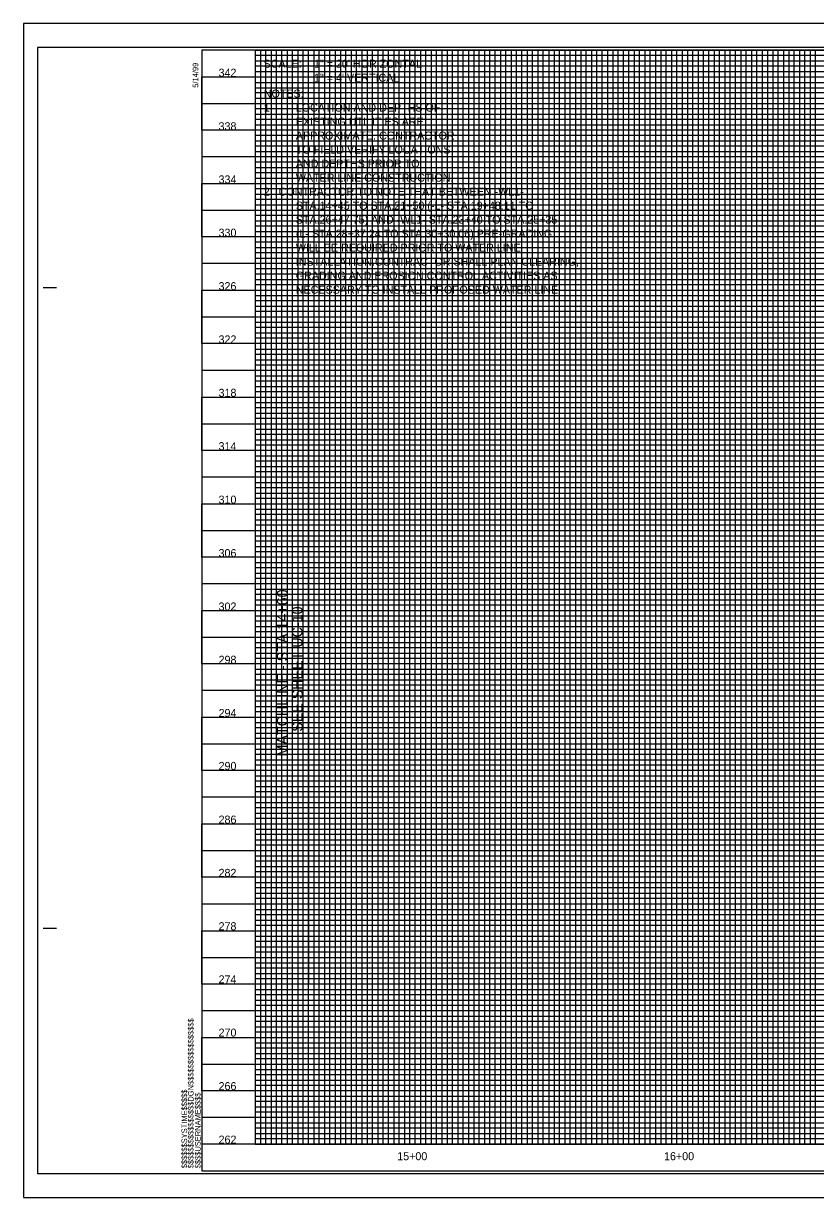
# Model space of a CAD drawing. Extents: x 3814791 to 3815465, y 1224203 to 1224643.
# Drawn here: x 3814791.3 to 3815088.1, y 1224203.2 to 1224643.2 of the extents above; entities that cross this region are included whole.
import ezdxf

# ---------------------------------------------------------------- set-up
doc = ezdxf.new("R2010")
doc.units = 0
for name, color, linetype in [('COGO Default Spiral', 7, 'Continuous'), ('Exist Roads EOP', 7, 'Continuous'), ('General Text and Text Box and Leader Line', 7, 'Continuous'), ('Pattern 49', 7, 'Continuous'), ('Profile Utility Text', 7, 'Continuous'), ('Scratch_Level_1', 7, 'Continuous'), ('Water Line Text and Text Box and Leader Line (St)', 7, 'Continuous'), ('Water Pump Station (St) CELL', 7, 'Continuous')]:
    doc.layers.add(name, color=color, linetype=linetype)

msp = doc.modelspace()

# ---------------------------------------------------------------- linework, layer by layer
at = {"layer": 'COGO Default Spiral'}
msp.add_line((3814898.11, 1224523.21), (3814898.11, 1224283.21), dxfattribs=at)
at = {"layer": 'Exist Roads EOP'}
for p, q in [((3814878.11, 1224633.21), (3815378.11, 1224633.21)), ((3815438.11, 1224561.21), (3814878.11, 1224561.21)), ((3814878.11, 1224561.21), (3814878.11, 1224559.21)), ((3814878.11, 1224559.21), (3815438.11, 1224559.21)), ((3815438.11, 1224551.21), (3814878.11, 1224551.21)), ((3814798.71, 1224544.21), (3814803.71, 1224544.21)), ((3814798.71, 1224304.21), (3814803.71, 1224304.21)), ((3815458.11, 1224223.21), (3814858.11, 1224223.21)), ((3814878.11, 1224223.21), (3815438.11, 1224223.21)), ((3814858.11, 1224213.21), (3814858.11, 1224213.21)), ((3814858.11, 1224213.21), (3814858.11, 1224213.21)), ((3814858.11, 1224213.21), (3814858.11, 1224213.21)), ((3814858.11, 1224213.21), (3814858.11, 1224213.21)), ((3814858.11, 1224213.21), (3814858.11, 1224213.21)), ((3814858.11, 1224213.21), (3814858.11, 1224213.21))]:
    msp.add_line(p, q, dxfattribs=at)
for points in [[(3815458.11, 1224633.21), (3814858.11, 1224633.21), (3814858.11, 1224213.21), (3815458.11, 1224213.21)], [(3814878.11, 1224633.21), (3814878.11, 1224223.21), (3815438.11, 1224223.21), (3815438.11, 1224578.19), (3815378.11, 1224578.19), (3815378.11, 1224633.21)]]:
    msp.add_lwpolyline(points, close=True, dxfattribs=at)
for points in [[(3814878.11, 1224633.21), (3814878.11, 1224223.21), (3814898.11, 1224223.21), (3814898.11, 1224633.21), (3814918.11, 1224633.21), (3814918.11, 1224223.21), (3814938.11, 1224223.21), (3814938.11, 1224633.21), (3814958.11, 1224633.21), (3814958.11, 1224223.21), (3814978.11, 1224223.21), (3814978.11, 1224633.21), (3814998.11, 1224633.21), (3814998.11, 1224223.21), (3815018.11, 1224223.21), (3815018.11, 1224633.21), (3815038.11, 1224633.21), (3815038.11, 1224223.21), (3815058.11, 1224223.21), (3815058.11, 1224633.21), (3815078.11, 1224633.21), (3815078.11, 1224223.21), (3815098.11, 1224223.21)], [(3814878.11, 1224633.21), (3814880.11, 1224633.21), (3814880.11, 1224223.21), (3814882.11, 1224223.21), (3814882.11, 1224633.21), (3814884.11, 1224633.21), (3814884.11, 1224223.21), (3814886.11, 1224223.21), (3814886.11, 1224633.21), (3814890.11, 1224633.21), (3814890.11, 1224223.21), (3814892.11, 1224223.21), (3814892.11, 1224633.21), (3814894.11, 1224633.21), (3814894.11, 1224223.21), (3814896.11, 1224223.21), (3814896.11, 1224633.21), (3814900.11, 1224633.21), (3814900.11, 1224223.21), (3814902.11, 1224223.21), (3814902.11, 1224633.21), (3814904.11, 1224633.21), (3814904.11, 1224223.21), (3814906.11, 1224223.21), (3814906.11, 1224633.21), (3814910.11, 1224633.21), (3814910.11, 1224223.21), (3814912.11, 1224223.21), (3814912.11, 1224633.21), (3814914.11, 1224633.21), (3814914.11, 1224223.21), (3814916.11, 1224223.21), (3814916.11, 1224633.21), (3814920.11, 1224633.21), (3814920.11, 1224223.21), (3814922.11, 1224223.21), (3814922.11, 1224633.21), (3814924.11, 1224633.21), (3814924.11, 1224223.21), (3814926.11, 1224223.21), (3814926.11, 1224633.21), (3814930.11, 1224633.21), (3814930.11, 1224223.21), (3814932.11, 1224223.21), (3814932.11, 1224633.21), (3814934.11, 1224633.21), (3814934.11, 1224223.21), (3814936.11, 1224223.21), (3814936.11, 1224633.21), (3814940.11, 1224633.21), (3814940.11, 1224223.21), (3814942.11, 1224223.21), (3814942.11, 1224633.21), (3814944.11, 1224633.21), (3814944.11, 1224223.21)], [(3815378.09, 1224631.21), (3814878.11, 1224631.21), (3814878.11, 1224629.21), (3815378.09, 1224629.21)], [(3814888.11, 1224223.21), (3814888.11, 1224633.21), (3814908.11, 1224633.21), (3814908.11, 1224223.21), (3814928.11, 1224223.21), (3814928.11, 1224633.21), (3814948.11, 1224633.21), (3814948.11, 1224223.21), (3814968.11, 1224223.21), (3814968.11, 1224633.21), (3814988.11, 1224633.21), (3814988.11, 1224223.21), (3815008.11, 1224223.21), (3815008.11, 1224633.21), (3815028.11, 1224633.21), (3815028.11, 1224223.21), (3815048.11, 1224223.21), (3815048.11, 1224633.21), (3815068.11, 1224633.21), (3815068.11, 1224223.21), (3815088.11, 1224223.21), (3815088.11, 1224633.21)], [(3814944.11, 1224223.21), (3814946.11, 1224223.21), (3814946.11, 1224633.21), (3814950.11, 1224633.21), (3814950.11, 1224223.21), (3814952.11, 1224223.21), (3814952.11, 1224633.21), (3814954.11, 1224633.21), (3814954.11, 1224223.21), (3814956.11, 1224223.21), (3814956.11, 1224633.21), (3814960.11, 1224633.21), (3814960.11, 1224223.21), (3814962.11, 1224223.21), (3814962.11, 1224633.21), (3814962.11, 1224633.21), (3814964.11, 1224633.21), (3814964.11, 1224223.21), (3814966.11, 1224223.21), (3814966.11, 1224633.21), (3814970.11, 1224633.21), (3814970.11, 1224223.21), (3814972.11, 1224223.21), (3814972.11, 1224633.21), (3814974.11, 1224633.21), (3814974.11, 1224223.21), (3814976.11, 1224223.21), (3814976.11, 1224633.21), (3814980.11, 1224633.21), (3814980.11, 1224223.21), (3814982.11, 1224223.21), (3814982.11, 1224633.21), (3814984.11, 1224633.21), (3814984.11, 1224223.21), (3814986.11, 1224223.21), (3814986.11, 1224633.21), (3814990.11, 1224633.21), (3814990.11, 1224223.21), (3814992.11, 1224223.21), (3814992.11, 1224633.21), (3814994.11, 1224633.21), (3814994.11, 1224223.21), (3814996.11, 1224223.21), (3814996.11, 1224633.21), (3815000.11, 1224633.21), (3815000.11, 1224223.21), (3815002.11, 1224223.21), (3815002.11, 1224633.21), (3815004.11, 1224633.21), (3815004.11, 1224223.21), (3815006.11, 1224223.21), (3815006.11, 1224633.21), (3815010.11, 1224633.21), (3815010.11, 1224223.21), (3815016.11, 1224223.21), (3815016.11, 1224633.21), (3815020.11, 1224633.21), (3815020.11, 1224223.21), (3815022.11, 1224223.21), (3815022.11, 1224633.21), (3815024.11, 1224633.21), (3815024.11, 1224223.21), (3815026.11, 1224223.21), (3815026.11, 1224633.21), (3815030.11, 1224633.21), (3815030.11, 1224223.21), (3815032.11, 1224223.21), (3815032.11, 1224633.21), (3815034.11, 1224633.21), (3815034.11, 1224223.21), (3815036.11, 1224223.21), (3815036.11, 1224633.21), (3815040.11, 1224633.21), (3815040.11, 1224223.21), (3815042.11, 1224223.21), (3815042.11, 1224633.21), (3815044.11, 1224633.21), (3815044.11, 1224223.21), (3815046.11, 1224223.21), (3815046.11, 1224633.21), (3815050.11, 1224633.21), (3815050.11, 1224223.21), (3815052.11, 1224223.21), (3815052.11, 1224633.21), (3815054.11, 1224633.21), (3815054.11, 1224223.21), (3815056.11, 1224223.21), (3815056.11, 1224633.21), (3815060.11, 1224633.21), (3815060.11, 1224223.21), (3815062.11, 1224223.21), (3815062.11, 1224633.21), (3815064.11, 1224633.21), (3815064.11, 1224223.21), (3815066.11, 1224223.21), (3815066.11, 1224633.21), (3815070.11, 1224633.21), (3815070.11, 1224223.21)], [(3815012.11, 1224633.21), (3815012.11, 1224223.21), (3815014.11, 1224223.21), (3815014.11, 1224633.21)], [(3815012.11, 1224632.97), (3815012.11, 1224223.21), (3815014.11, 1224223.21), (3815014.11, 1224632.97)], [(3815072.11, 1224633.21), (3815072.11, 1224223.21), (3815074.11, 1224223.21), (3815074.11, 1224633.21), (3815076.11, 1224633.21), (3815076.11, 1224223.21), (3815080.11, 1224223.21), (3815080.11, 1224633.21), (3815082.11, 1224633.21), (3815082.11, 1224223.21), (3815084.11, 1224223.21), (3815084.11, 1224633.21), (3815086.11, 1224633.21), (3815086.11, 1224223.21)], [(3815378.09, 1224627.21), (3814878.11, 1224627.21), (3814878.11, 1224625.21), (3815378.09, 1224625.21)], [(3815378.09, 1224603.21), (3814858.15, 1224603.21), (3814858.15, 1224623.19), (3815378.09, 1224623.19)], [(3815378.09, 1224620.91), (3814878.11, 1224620.91)], [(3815378.09, 1224618.91), (3814878.11, 1224618.91)], [(3815378.09, 1224617.21), (3814878.11, 1224617.21), (3814878.11, 1224615.21), (3815378.09, 1224615.21)], [(3814858.11, 1224613.21), (3815378.09, 1224613.21)], [(3815378.09, 1224611.21), (3814878.11, 1224611.21), (3814878.11, 1224609.21), (3815378.09, 1224609.21)], [(3815378.11, 1224607.21), (3814878.11, 1224607.21), (3814878.11, 1224605.21), (3815378.09, 1224605.21)], [(3815378.09, 1224601.21), (3814878.11, 1224601.21), (3814878.11, 1224599.21), (3815378.09, 1224599.21)], [(3815378.09, 1224597.21), (3814878.11, 1224597.21), (3814878.11, 1224595.21), (3815378.09, 1224595.21)], [(3815378.09, 1224593.21), (3814858.11, 1224593.21), (3814858.11, 1224573.19), (3815458.11, 1224573.19)], [(3815378.09, 1224591.21), (3814878.11, 1224591.21), (3814878.11, 1224589.21), (3815378.09, 1224589.21)], [(3815378.09, 1224587.21), (3814878.11, 1224587.21), (3814878.11, 1224585.21), (3815378.09, 1224585.21)], [(3815458.11, 1224563.21), (3814858.11, 1224563.21), (3814858.11, 1224583.21), (3815378.09, 1224583.21)], [(3815378.09, 1224581.21), (3814878.11, 1224581.21), (3814878.11, 1224579.21), (3815378.09, 1224579.21)], [(3815438.11, 1224577.21), (3814878.11, 1224577.21), (3814878.11, 1224577.21), (3814878.11, 1224569.21), (3815438.11, 1224569.21)], [(3814878.11, 1224575.21), (3815438.11, 1224575.21)], [(3815438.11, 1224571.21), (3814878.11, 1224571.21)], [(3815438.11, 1224567.21), (3814878.11, 1224567.21), (3814878.11, 1224565.21), (3815438.11, 1224565.21)], [(3815438.11, 1224557.21), (3814878.11, 1224557.21), (3814878.11, 1224555.21), (3815438.11, 1224555.21)], [(3815458.11, 1224553.21), (3814858.11, 1224553.21), (3814858.11, 1224533.21), (3815458.11, 1224533.21)], [(3815438.11, 1224549.21), (3814878.11, 1224549.21), (3814878.11, 1224547.21), (3815438.11, 1224547.21)], [(3815458.11, 1224523.21), (3814858.11, 1224523.21), (3814858.11, 1224543.21), (3815458.11, 1224543.21)], [(3815438.11, 1224545.21), (3814878.11, 1224545.21)], [(3814878.11, 1224541.21), (3815438.11, 1224541.21)], [(3815438.11, 1224539.21), (3814878.11, 1224539.21), (3814878.11, 1224537.21), (3815438.11, 1224537.21)], [(3815438.11, 1224535.21), (3814878.11, 1224535.21), (3814878.11, 1224531.21), (3815438.11, 1224531.21)], [(3815438.11, 1224529.21), (3814878.11, 1224529.21), (3814878.11, 1224527.21), (3815438.11, 1224527.21)], [(3815438.11, 1224525.21), (3814878.11, 1224525.21), (3814878.11, 1224521.21), (3815438.11, 1224521.21)], [(3815438.11, 1224519.21), (3814878.11, 1224519.21), (3814878.11, 1224517.21), (3815438.11, 1224517.21)], [(3815458.11, 1224513.21), (3814858.11, 1224513.21), (3814858.11, 1224493.21), (3815458.11, 1224493.21)], [(3815438.11, 1224515.21), (3814878.11, 1224515.21), (3814878.11, 1224511.21), (3815438.11, 1224511.21)], [(3815438.11, 1224509.21), (3814878.11, 1224509.21), (3814878.11, 1224507.21), (3815438.11, 1224507.21)], [(3815458.11, 1224483.21), (3814858.11, 1224483.21), (3814858.11, 1224503.21), (3815458.11, 1224503.21)], [(3815438.11, 1224505.21), (3814878.11, 1224505.21), (3814878.11, 1224501.21), (3815438.11, 1224501.21)], [(3815438.11, 1224499.21), (3814878.11, 1224499.21), (3814878.11, 1224497.21), (3815438.11, 1224497.21)], [(3815438.11, 1224495.21), (3814878.11, 1224495.21), (3814878.11, 1224491.21), (3815438.11, 1224491.21)], [(3815438.11, 1224489.21), (3814878.11, 1224489.21), (3814878.11, 1224487.21), (3815438.11, 1224487.21)], [(3815438.11, 1224485.21), (3814878.11, 1224485.21), (3814878.11, 1224481.21), (3815438.11, 1224481.21)], [(3815438.11, 1224479.21), (3814878.11, 1224479.21), (3814878.11, 1224477.21), (3815438.11, 1224477.21)], [(3815458.11, 1224473.21), (3814858.11, 1224473.21), (3814858.11, 1224453.21), (3815458.11, 1224453.21)], [(3815438.11, 1224475.21), (3814878.11, 1224475.21), (3814878.11, 1224471.21), (3815438.11, 1224471.21)], [(3815438.11, 1224469.21), (3814878.11, 1224469.21), (3814878.11, 1224467.21), (3815438.11, 1224467.21)], [(3815458.11, 1224443.21), (3814858.11, 1224443.21), (3814858.11, 1224463.21), (3815458.11, 1224463.21)], [(3815438.11, 1224465.21), (3814878.11, 1224465.21), (3814878.11, 1224461.21), (3815438.11, 1224461.21)], [(3815438.11, 1224459.21), (3814878.11, 1224459.21), (3814878.11, 1224457.21), (3815438.11, 1224457.21)], [(3815438.11, 1224455.21), (3814878.11, 1224455.21), (3814878.11, 1224451.21), (3815438.11, 1224451.21)], [(3815438.11, 1224449.21), (3814878.11, 1224449.21), (3814878.11, 1224447.21), (3815438.11, 1224447.21)], [(3815438.11, 1224445.21), (3814878.11, 1224445.21), (3814878.11, 1224441.21), (3815438.11, 1224441.21)], [(3815438.11, 1224439.21), (3814878.11, 1224439.21), (3814878.11, 1224437.21), (3815438.11, 1224437.21)], [(3815458.11, 1224433.21), (3814858.11, 1224433.21), (3814858.11, 1224413.21), (3815458.11, 1224413.21)], [(3815438.11, 1224435.21), (3814878.11, 1224435.21), (3814878.11, 1224431.21), (3815438.11, 1224431.21)], [(3815438.11, 1224429.21), (3814878.11, 1224429.21), (3814878.11, 1224427.21), (3815438.11, 1224427.21)], [(3815458.11, 1224403.21), (3814858.11, 1224403.21), (3814858.11, 1224423.21), (3815458.11, 1224423.21)], [(3815438.11, 1224425.21), (3814878.11, 1224425.21)], [(3814878.11, 1224421.21), (3815438.11, 1224421.21)], [(3815438.11, 1224419.21), (3814878.11, 1224419.21), (3814878.11, 1224417.21), (3815438.11, 1224417.21)], [(3815438.11, 1224415.21), (3814878.11, 1224415.21), (3814878.11, 1224411.21), (3815438.11, 1224411.21)], [(3815438.11, 1224409.21), (3814878.11, 1224409.21), (3814878.11, 1224407.21), (3815438.11, 1224407.21)], [(3815438.11, 1224405.21), (3814878.11, 1224405.21), (3814878.11, 1224401.21), (3815438.11, 1224401.21)], [(3815438.11, 1224399.21), (3814878.11, 1224399.21), (3814878.11, 1224397.21), (3815438.11, 1224397.21)], [(3815458.11, 1224393.21), (3814858.11, 1224393.21), (3814858.11, 1224373.21), (3815458.11, 1224373.21)], [(3815438.11, 1224395.21), (3814878.11, 1224395.21), (3814878.11, 1224391.21), (3815438.11, 1224391.21)], [(3815438.11, 1224389.21), (3814878.11, 1224389.21), (3814878.11, 1224387.21), (3815438.11, 1224387.21)], [(3815438.11, 1224385.21), (3814878.11, 1224385.21), (3814878.11, 1224381.21), (3815438.11, 1224381.21)], [(3815458.11, 1224363.21), (3814858.11, 1224363.21), (3814858.11, 1224383.21), (3815458.11, 1224383.21)], [(3815438.11, 1224379.21), (3814878.11, 1224379.21), (3814878.11, 1224377.21), (3815438.11, 1224377.21)], [(3815438.11, 1224375.21), (3814878.11, 1224375.21), (3814878.11, 1224371.21), (3815438.11, 1224371.21)], [(3815438.11, 1224369.21), (3814878.11, 1224369.21), (3814878.11, 1224367.21), (3815438.11, 1224367.21)], [(3815438.11, 1224365.21), (3814878.11, 1224365.21), (3814878.11, 1224361.21), (3815438.11, 1224361.21)], [(3815438.11, 1224359.21), (3814878.11, 1224359.21), (3814878.11, 1224357.21), (3815438.11, 1224357.21)], [(3815458.11, 1224353.21), (3814858.11, 1224353.21), (3814858.11, 1224333.21), (3815458.11, 1224333.21)], [(3815438.11, 1224355.21), (3814878.11, 1224355.21), (3814878.11, 1224351.21), (3815438.11, 1224351.21)], [(3815438.11, 1224349.21), (3814878.11, 1224349.21), (3814878.11, 1224347.21), (3815438.11, 1224347.21)], [(3815438.11, 1224345.21), (3814878.11, 1224345.21), (3814878.11, 1224341.21), (3815438.11, 1224341.21)], [(3815458.11, 1224323.21), (3814858.11, 1224323.21), (3814858.11, 1224343.21), (3815458.11, 1224343.21)], [(3815438.11, 1224339.21), (3814878.11, 1224339.21), (3814878.11, 1224337.21), (3815438.11, 1224337.21)], [(3815438.11, 1224335.21), (3814878.11, 1224335.21), (3814878.11, 1224331.21), (3815438.11, 1224331.21)], [(3815438.11, 1224329.21), (3814878.11, 1224329.21), (3814878.11, 1224327.21), (3815438.11, 1224327.21)], [(3815438.11, 1224325.21), (3814878.11, 1224325.21), (3814878.11, 1224321.21), (3815438.11, 1224321.21)], [(3815438.11, 1224319.21), (3814878.11, 1224319.21), (3814878.11, 1224317.21), (3815438.11, 1224317.21)], [(3815458.11, 1224313.21), (3814858.11, 1224313.21), (3814858.11, 1224293.21), (3815458.11, 1224293.21)], [(3815438.11, 1224315.21), (3814878.11, 1224315.21), (3814878.11, 1224311.21), (3815438.11, 1224311.21)], [(3815438.11, 1224309.21), (3814878.11, 1224309.21), (3814878.11, 1224307.21), (3815438.11, 1224307.21)], [(3815438.11, 1224305.21), (3814878.11, 1224305.21)], [(3815458.11, 1224283.21), (3814858.11, 1224283.21), (3814858.11, 1224303.21), (3815458.11, 1224303.21)], [(3814878.11, 1224301.21), (3815438.11, 1224301.21)], [(3815438.11, 1224299.21), (3814878.11, 1224299.21), (3814878.11, 1224297.21), (3815438.11, 1224297.21)], [(3815438.11, 1224295.21), (3814878.11, 1224295.21)], [(3814878.11, 1224291.21), (3815438.11, 1224291.21)], [(3815438.11, 1224289.21), (3814878.11, 1224289.21), (3814878.11, 1224287.21), (3815438.11, 1224287.21)], [(3815438.11, 1224285.21), (3814878.11, 1224285.21), (3814878.11, 1224281.21), (3815438.11, 1224281.21)], [(3815438.11, 1224279.21), (3814878.11, 1224279.21), (3814878.11, 1224277.21), (3815438.11, 1224277.21)], [(3815438.11, 1224275.21), (3814878.11, 1224275.21), (3814878.11, 1224271.21), (3815438.11, 1224271.21)], [(3815458.11, 1224273.21), (3814858.11, 1224273.21), (3814858.11, 1224253.21), (3815458.11, 1224253.21)], [(3815438.11, 1224269.21), (3814878.11, 1224269.21), (3814878.11, 1224267.21), (3815438.11, 1224267.21)], [(3815438.11, 1224265.21), (3814878.11, 1224265.21), (3814878.11, 1224261.21), (3815438.11, 1224261.21)], [(3815458.11, 1224243.21), (3814858.11, 1224243.21), (3814858.11, 1224263.21), (3815458.11, 1224263.21)], [(3815438.11, 1224259.21), (3814878.11, 1224259.21), (3814878.11, 1224257.21), (3815438.11, 1224257.21)], [(3815438.11, 1224255.21), (3814878.11, 1224255.21), (3814878.11, 1224251.21), (3815438.11, 1224251.21)], [(3815438.11, 1224249.21), (3814878.11, 1224249.21), (3814878.11, 1224247.21), (3815438.11, 1224247.21)], [(3815438.11, 1224245.21), (3814878.11, 1224245.21), (3814878.11, 1224241.21), (3815438.11, 1224241.21)], [(3815438.11, 1224239.21), (3814878.11, 1224239.21), (3814878.11, 1224237.21), (3815438.11, 1224237.21)], [(3815438.11, 1224235.21), (3814878.11, 1224235.21), (3814878.11, 1224231.21), (3815438.11, 1224231.21)], [(3815458.11, 1224233.21), (3814858.11, 1224233.21)], [(3815438.11, 1224229.21), (3814878.11, 1224229.21), (3814878.11, 1224227.21), (3815438.11, 1224227.21)], [(3815438.11, 1224225.21), (3814878.11, 1224225.21)], [(3814873.11, 1224213.21), (3814873.11, 1224213.21)]]:
    msp.add_lwpolyline(points, dxfattribs=at)
at = {"layer": 'Pattern 49'}
msp.add_lwpolyline([(3815463.11, 1224634.23), (3814796.51, 1224634.23), (3814796.51, 1224212.19), (3815463.11, 1224212.19)], close=True, dxfattribs=at)
at = {"layer": 'Scratch_Level_1'}
msp.add_lwpolyline([(3815464.91, 1224643.21), (3814791.31, 1224643.21), (3814791.31, 1224203.21), (3815464.91, 1224203.21)], close=True, dxfattribs=at)

# ---------------------------------------------------------------- texts
at = {"layer": 'Exist Roads EOP'}
for s, p in [('5/14/99', (3814856.81, 1224619.13)), ('5/14/99', (3814856.81, 1224619.13)), ('$$$$$$$$$$$$$$$$DGN$$$$$$$$$$$$$$$$', (3814855.05, 1224214.15)), ('$$$$$$SYSTIME$$$$$', (3814852.63, 1224214.15)), ('$$$$USERNAME$$$$', (3814857.68, 1224214.16))]:
    msp.add_text(s, height=2.1, rotation=90, dxfattribs=at).set_placement(p)
at = {"layer": 'General Text and Text Box and Leader Line'}
for s, p in [('342', (3814864.41, 1224623.26)), ('338', (3814864.41, 1224603.19)), ('334', (3814864.41, 1224583.27)), ('330', (3814864.41, 1224563.3)), ('326', (3814864.41, 1224543.26)), ('322', (3814864.41, 1224523.3)), ('318', (3814864.41, 1224503.3)), ('314', (3814864.41, 1224483.29)), ('310', (3814864.41, 1224463.26)), ('306', (3814864.41, 1224443.22)), ('302', (3814864.41, 1224423.2)), ('298', (3814864.41, 1224403.25)), ('294', (3814864.41, 1224383.29)), ('290', (3814864.41, 1224363.45)), ('286', (3814864.41, 1224343.34)), ('282', (3814864.41, 1224323.38)), ('278', (3814864.41, 1224303.38)), ('274', (3814864.41, 1224283.48)), ('270', (3814864.41, 1224263.52)), ('266', (3814864.41, 1224243.46)), ('262', (3814864.41, 1224223.4))]:
    msp.add_text(s, height=3, dxfattribs=at).set_placement(p)
at = {"layer": 'Profile Utility Text'}
for s, p in [('SCALE: ', (3814881.28, 1224626.62)), ('1" = 20\' HORIZONTAL', (3814900.19, 1224626.62)), ('1" = 4\' VERTICAL', (3814900.19, 1224621.37)), ('NOTES:', (3814881.36, 1224615.43)), ('1.', (3814881.36, 1224610.18)), ('LOCATION AND DEPTHS OF', (3814893.36, 1224610.18)), ('EXISTING UTILITIES ARE', (3814893.36, 1224604.94)), ('APPROXIMATE. CONTRACTOR', (3814893.36, 1224599.69)), ('TO FIELD VERIFY LOCATIONS', (3814893.36, 1224594.44)), ('AND DEPTHS PRIOR TO', (3814893.36, 1224589.19)), ('WATER LINE CONSTRUCTION.', (3814893.36, 1224583.94)), ('2.  CONTRACTOR TO NOTE THAT BETWEEN -WL1-', (3814881.36, 1224578.69)), ('STA.14+45 TO STA.21+50 (-L- STA.19+48.11 TO', (3814893.36, 1224573.44)), ('STA.26+47.75) AND -WL1- STA.23+40 TO STA.25+35', (3814893.36, 1224568.2)), ('(L- STA.28+37.24 TO STA.30+30.06) PRE-GRADING', (3814893.36, 1224562.95)), ('WILL BE REQUIRED PRIOR TO WATER LINE', (3814893.36, 1224557.7)), ('INSTALLATION.CONTRACTOR SHALL PLAN CLEARING,', (3814893.36, 1224552.45)), ('GRADING AND EROSION CONTROL ACTIVITIES AS', (3814893.36, 1224547.2)), ('NECESSARY TO INSTALL PROPOSED WATER LINE.', (3814893.36, 1224541.95))]:
    msp.add_text(s, height=3, dxfattribs=at).set_placement(p)
at = {"layer": 'Water Line Text and Text Box and Leader Line (St)'}
for s, p in [('MATCHLINE - STA.14+60', (3814890.3, 1224368.51)), ('SEE SHEET UC-10', (3814895.9, 1224377.76))]:
    msp.add_text(s, height=4, rotation=90, dxfattribs=at).set_placement(p)
at = {"layer": 'Water Pump Station (St) CELL'}
for s, p in [('15+00', (3814931.36, 1224217.19)), ('16+00', (3815031.34, 1224217.19))]:
    msp.add_text(s, height=3, dxfattribs=at).set_placement(p)

doc.saveas('drawing.dxf')
